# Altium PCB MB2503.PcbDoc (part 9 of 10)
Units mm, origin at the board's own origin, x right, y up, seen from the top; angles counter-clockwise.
Board outline 127 x 97 mm, 6 copper layers (Top Layer, Signal Layer 1, Signal Layer 2, Signal Layer 3, Signal Layer 4, Bottom Layer), stack 1.557 mm thick; 572 components, 468 nets, 2377 pads, 1704 vias.
Unrouted connection lines stored in the file: 3.
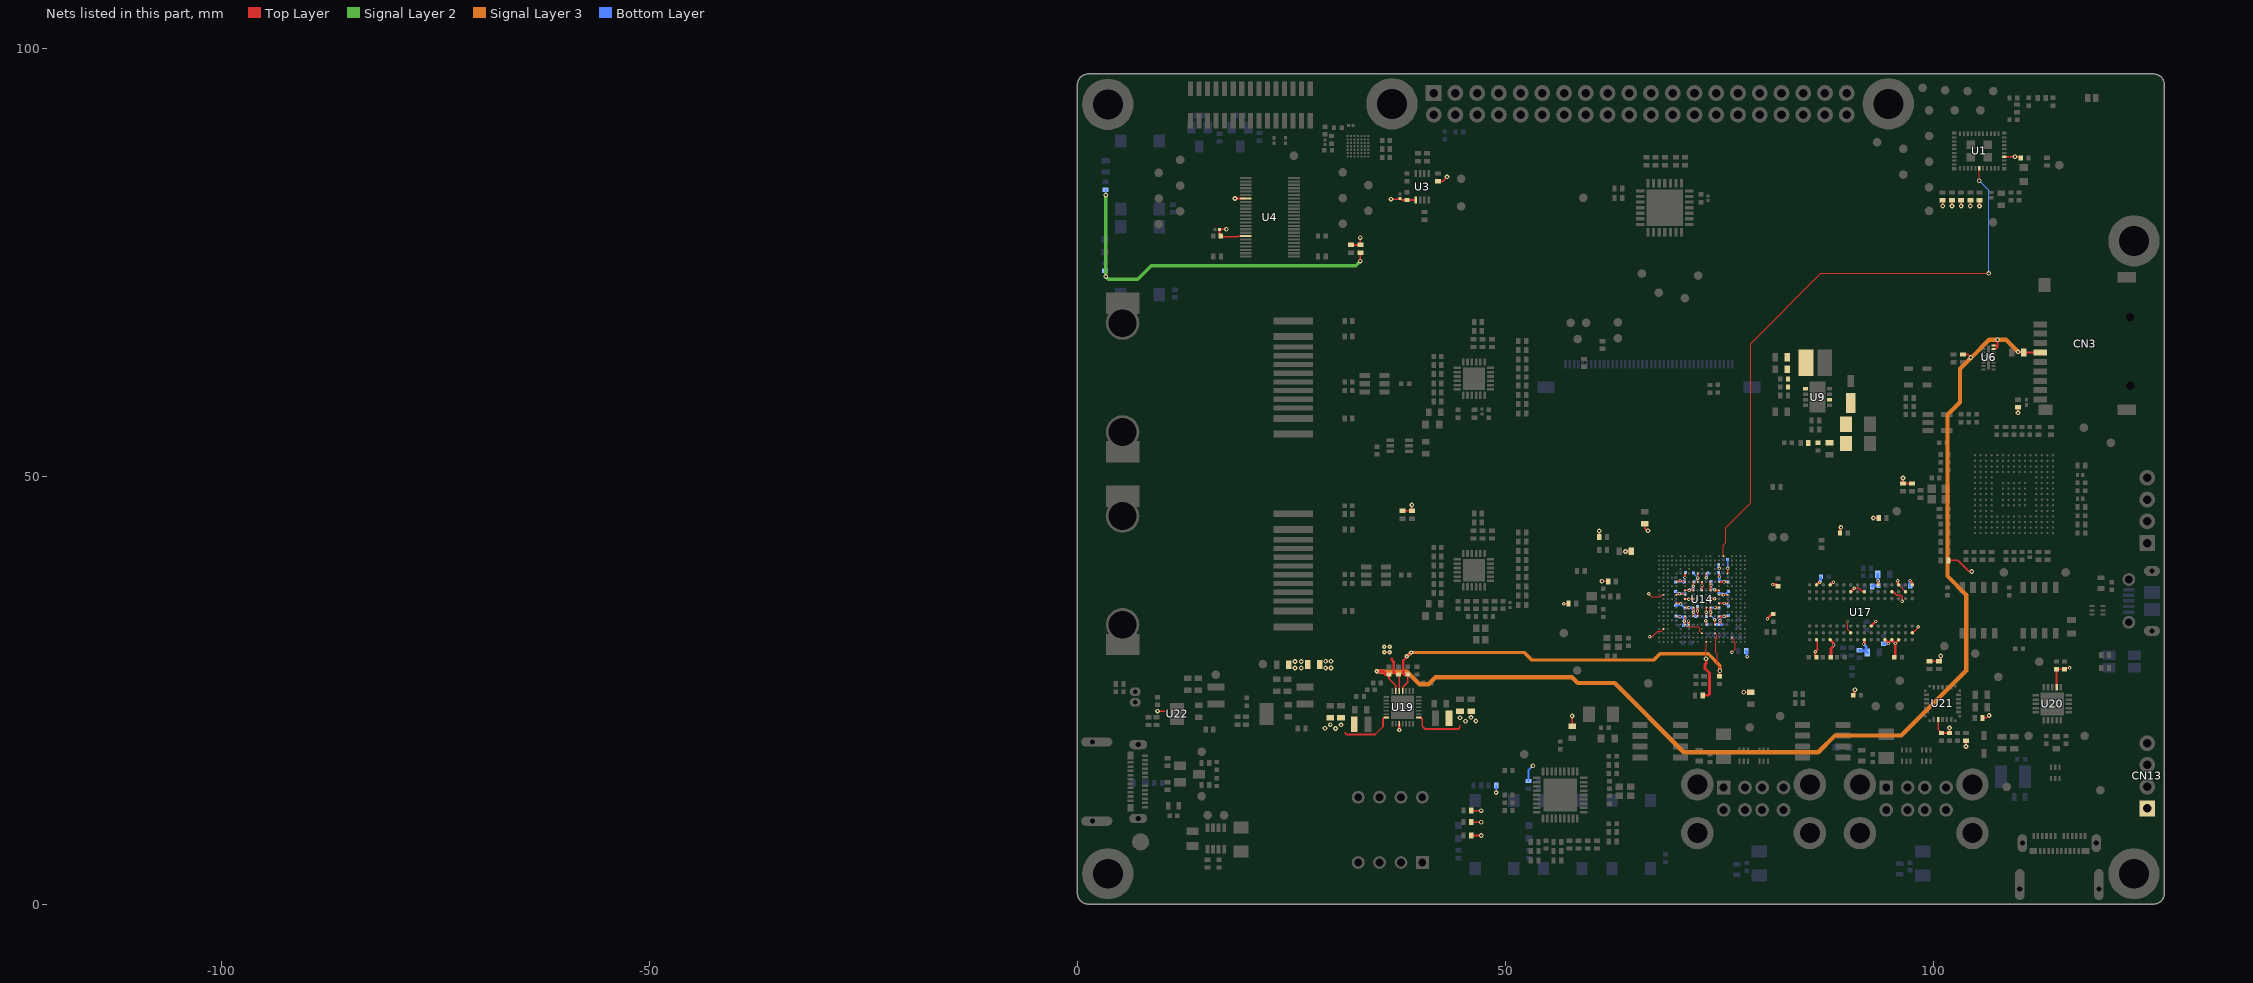
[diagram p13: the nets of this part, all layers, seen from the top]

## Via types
v1: diameter 0.55, hole 0.25, Top Layer to Bottom Layer, 1335 vias
v2: diameter 0.4, hole 0.2, Top Layer to Bottom Layer, 262 vias
v3: diameter 0.5, hole 0.2, Top Layer to Bottom Layer, 51 vias
v4: diameter 0.26, hole 0.1, Top Layer to Signal Layer 1, tented both sides, 29 vias
v5: diameter 0.5, hole 0.25, Top Layer to Bottom Layer, 18 vias
v6: diameter 0.4, hole 0.2, Top Layer to Bottom Layer, tented both sides, 9 vias

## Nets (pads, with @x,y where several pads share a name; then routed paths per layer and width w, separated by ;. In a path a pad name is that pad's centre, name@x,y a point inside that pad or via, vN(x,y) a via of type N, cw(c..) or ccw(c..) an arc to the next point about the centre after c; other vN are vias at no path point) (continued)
VDD: C15.2 C108.2 C109.2 C111.2 C138.2 C139.2 C171.2 C173.2 C176.2 C185.1 C190.2 C197.2 C201.2 C202.2 C205.2 C207.1 C208.2 C209.2 C214.1 C215.1 CN13.1 R14.1 R15.1 R16.1 R17.1 R18.1 R21.2 R46.1 R62.2 R63.2 R71.2 R72.2 R75.2 R82.2 R94.2 R108.2 R120.2 R121.1 R133.2 R141.2 R153.2 R154.2 R155.2 R172.2 R174.2 R180.2 R181.2 R187.2 R192.2 U1.36 U14.AA12 U14.C15 U14.E12 U14.E17 U14.G9 U14.G13 U14.J7 U14.J9 U14.J13 U14.K2 U14.M5 U14.N7 U14.N9 U14.N12 U14.R5 U14.R7 U14.R9 U14.R12 U14.U7 U14.U8 U14.V2 U14.W11 U14.Y18 U19.3 U19.19 U20.2 U21.3 U22.2 | length 117.3
  Top Layer w0.075: v2@66.75,36.2 67.046,35.904 68.079,35.904 68.302,36.127 68.452,36.127 U14.K2@68.475,36.15 ; v2(66.85,31.225) 67.15,31.225 67.825,31.9 68.225,31.9 U14.V2@68.475,32.15 ; U14.U7@70.975,32.65 71.224,32.401 72.512,32.401 72.727,32.187 72.727,32.186 72.728,32.184 72.728,31.897 U14.W11@72.975,31.65 ; v2(76.475,29.425) 76.85,29.8 76.85,30.425 76.725,30.55 76.725,30.899 U14.Y18@76.474,31.15
  Top Layer w0.09: v2@66.75,36.2 v2(66.75,36.25) ; U14.R5@69.975,33.65 70.002,33.623 70.405,33.623 70.449,33.58 70.444,33.575 v2(70.4,33.575) ; v1(73.45,28.675) 73.425,28.7 73.425,29.7 73.475,29.75 U14.AA12@73.475,30.65 ; U14.C15@74.975,39.65 74.988,39.638 74.988,39.188 75,39.2 v2(75,39.225)
  Top Layer w0.175: U14.J7@70.975,36.65 v2(71.475,36.65) U14.J9@71.975,36.65 71.975,37.125 v2(71.95,37.15) ; U14.R12@73.475,33.65 73.45,33.675 v2(73.45,34.1) 73.45,34.625 U14.N12@73.475,34.65
  Top Layer w0.2: v1(9.35,22.55) U22.2@10.175,22.55 ; v1(33.05,75.125) R21.2@33.05,76.125 ; v3(35.851,29.426) v3(36.5,29.425) ; C111.2@37.5,26.825 37.6,26.725 U19.19@37.6,24.9 ; C111.2@37.55,26.875 C111.2@37.6,26.825 ; C111.2@37.6,26.85 C111.2@37.625,26.875 ; R75.2@38,45.95 R71.2@39.1,45.95 39.075,45.975 v1(39.075,46.625) ; R153.2@46,8.025 v1(47.175,8.025) ; R154.2@46,9.575 v1(47.175,9.575) ; R155.2@46,10.925 v1(47.175,10.925) ; v2(56.825,35.1) 57.325,35.1 R108.2@57.375,35.15 ; R82.2@60.975,42.875 v1(60.975,43.6) ; v1(61.275,37.725) R192.2@62,37.725 ; U14.M5@69.975,35.15 69.979,35.146 70.375,35.146 70.446,35.075 v2(70.5,35.075) ; v2(70.9,33.05) 70.9,33.042 70.884,33.027 70.875,33.036 70.914,33.075 70.95,33.039 70.925,33.014 70.975,32.964 U14.U7@70.975,32.65 ; v2@70.925,33.136 70.975,33.186 U14.R7@70.975,33.65 ; U14.N7@70.975,34.65 71.425,34.65 v2(71.45,34.625) ; v2(71.4,33.075) 71.4,32.725 U14.U8@71.475,32.65 ; v2(71.95,37.15) 71.969,37.169 71.969,37.623 71.969,37.644 U14.G9@71.975,37.65 ; U14.R9@71.975,33.65 71.975,34.075 v2(71.95,34.1) 71.975,34.125 U14.N9@71.975,34.65 ; v2@73.475,38.148 U14.E12@73.475,38.65 ; U14.J13@73.975,36.65 73.975,37.178 74,37.203 v2@74,37.25 ; U14.G13@73.975,37.65 73.975,37.225 v2@74,37.25 ; v2(74.022,37.269) 74.02,37.269 v2@74,37.25 ; U14.E17@75.975,38.65 v2(75.975,39.225) ; v1(93,45.125) R72.2@93.625,45.125 ; v1(96.45,49.8) R62.2@96.45,49.15 R63.2@97.525,49.15 ; R120.2@99.575,28.375 R121.1@100.65,28.375 100.775,28.25 100.875,28.35 v1(100.875,29) ; U21.3@100.575,21.575 100.575,20.4 C138.2@100.975,20 C139.2@101.9,20 v1(101.9,20.6) ; v1(101.1,81.575) R14.1@101.1,82.25 ; R94.2@101.775,40.175 102.875,40.175 104.139,38.911 104.448,38.911 v1(104.5,38.858) ; v1(102.175,81.575) R15.1@102.175,82.25 ; v1(103.25,81.575) R16.1@103.25,82.25 ; v1(103.825,18.425) R141.2@103.825,19.1 ; v1(104.325,81.575) R17.1@104.325,82.25 ; v1(105.4,81.575) R18.1@105.4,82.25 ; R187.2@105.75,21.775 106.25,21.775 v1(106.525,22.05) ; U1.36@108.3,87.325 110.075,87.325 C15.2@110.225,87.175 ; v1(109.9,57.4) R46.1@109.9,58.05 ; U20.2@114.4,25.325 C108.2@114.4,27.45 C109.2@115.325,27.45 115.437,27.562 115.912,27.562 v2(115.95,27.6)
  Top Layer w0.25: v3(37.6,20.35) U19.3@37.6,21.1
  Top Layer w0.3: 36.725,28.65 36.725,28.53 36.95,28.305 36.95,27.106 37.126,26.93 37.57,26.93 C111.2@37.62,26.88 ; R133.2@73.05,24.4 73.674,24.4 73.85,24.576 73.85,27 73.325,27.525 73.325,28.023 73.45,28.148 v1(73.45,28.675)
  Signal Layer 2 w0.4: v1(3.3,73.325) v1@3.3,73.343 ; v1(3.3,82.85) v1@3.3,73.343 ; v1(33.05,75.125) 32.525,74.6 8.625,74.6 7.05,73.025 3.618,73.025 v1@3.3,73.343
  Bottom Layer w0.09: C185.1@73.999,37.649 C185.1@74,37.65
  Bottom Layer w0.15: v2(70.5,35.075) 70.5,35.05 70.85,34.7 70.9,34.7 C201.2@71,34.6
  Bottom Layer w0.2: R174.2@3.205,73.988 3.3,73.893 v1(3.3,73.325) ; v1(3.3,82.85) 3.3,83.483 R172.2@3.305,83.488 ; v1(48.925,13.041) R181.2@48.925,13.85 ; R180.2@52.692,14.387 52.692,15.658 v1(53.209,16.175) ; v2@72.003,33.965 72.275,33.693 C209.2@72.275,33.6 ; C176.2@73.52,38.545 C176.2@73.65,38.675 ; v2(75.975,39.225) C171.2@75.975,40.275
  Bottom Layer w0.3: C207.1@69.975,33.675 70.075,33.575 v2(70.4,33.575) 70.916,33.575 70.92,33.58 C205.2@71,33.5 70.875,33.375 70.903,33.347 70.9,33.343 v2(70.9,33.05) 70.9,33.028 70.898,33.027 70.875,33.05 70.888,33.063 70.888,32.751 70.825,32.688 70.825,32.575 C215.1@70.8,32.55 ; C197.2@69.975,34.875 70,34.9 70.123,34.9 70.248,35.025 70.252,35.025 70.255,35.028 70.383,35.028 70.41,35.056 70.481,35.056 v2(70.5,35.075) ; C201.2@71,34.6 71.025,34.625 v2(71.45,34.625) 71.825,34.625 C202.2@71.9,34.55 71.95,34.5 v2(71.95,34.1) ; C214.1@71.375,32.525 C214.1@71.35,32.55 71.375,32.575 71.375,33.05 v2(71.4,33.075) ; v2(71.475,36.65) 71.531,36.706 71.559,36.706 71.603,36.75 C190.2@71.925,36.75 71.95,36.775 v2(71.95,37.15) ; v2(73.45,34.1) 73.45,33.775 73.475,33.75 C208.2@73.525,33.7 ; v2@73.52,38.193 C176.2@73.52,38.545 ; C185.1@73.999,37.649 74.022,37.625 v2(74.022,37.269) ; C173.2@74.875,39.7 74.875,39.35 v2(75,39.225)
  other v1: 109.55,87.325
  other v2: 73.474,38.147
  other v3: 35.85,30.075 36.5,30.075
VDD_CORE: C110.2 C124.2 C126.2 C133.2 C188.2 C189.2 C195.1 C196.2 C199.2 C200.2 C203.1 C213.2 L9.2 U14.G11 U14.J11 U14.J15 U14.L7 U14.L9 U14.L13 U14.N10 U14.N13 U14.N15 U14.R10 U14.R13 U14.U12 U14.U14 U19.8 | length 20.2
  Top Layer w0.2: U19.8@39.9,21.8 40.125,21.8 40.275,21.65 40.275,20.775 40.575,20.475 44.558,20.475 44.675,20.592 44.675,20.809 ; C133.2@57.8,20.8 v1(57.8,21.975) ; U14.L7@70.975,35.65 71.425,35.65 v2(71.45,35.625) 71.475,35.65 U14.L9@71.975,35.65 ; v2(72.45,34.225) 72.45,34.625 U14.N10@72.475,34.65 ; U14.R10@72.475,33.65 v2@72.475,34.225 ; U14.J11@72.975,36.65 v2@72.975,37.198 ; v2(72.975,37.225) v2@72.975,37.198 ; U14.G11@72.975,37.65 v2@72.975,37.198 ; U14.U12@73.475,32.65 73.475,32.875 v2@73.475,33.1 ; U14.R13@73.975,33.65 v2(73.975,34.1) ; U14.N13@73.975,34.65 v2@73.975,34.125 ; U14.L13@73.975,35.65 74.448,35.65 74.473,35.675 74.471,35.677 v2(74.454,35.677) ; v2(74.45,36.725) 74.525,36.65 U14.J15@74.974,36.65 ; U14.U14@74.475,32.65 v2@74.475,33.175 ; v2(74.5,34.65) U14.N15@74.975,34.65 ; v1(77.85,24.75) C124.2@78.65,24.75 ; v2(73.975,34.1) v2@73.975,34.125 ; v2(73.975,34.1) v2@73.975,34.125
  Bottom Layer w0.2: v2(71.45,35.625) 71.675,35.625 71.7,35.65 C196.2@71.925,35.65 ; v2(72.45,34.225) 72.45,34.55 72.475,34.575 C203.1@72.45,34.6 ; C189.2@72.9,36.75 72.975,36.825 72.975,37.149 v2(72.975,37.225) ; v2@73.5,33.086 73.494,33.081 73.494,32.706 C213.2@73.55,32.65 ; C195.1@74,35.7 74.025,35.675 74.396,35.675 74.422,35.649 74.449,35.677 v2(74.454,35.677) 74.454,35.673 74.475,35.651 v2@74.461,35.637 ; C188.2@74,36.8 74.375,36.8 v2(74.45,36.725) ; v2@74.473,34.65 74.448,34.625 74.025,34.625 C200.2@74,34.6 73.975,34.575 v2(73.975,34.1) 73.994,34.081 73.994,33.938 74.025,33.907 74.025,33.712 74.425,33.312 74.425,33.302 74.475,33.252 v2(74.475,33.225) v2@74.475,33.2 ; v2@74.475,34.65 v2(74.5,34.65) 74.513,34.638 74.963,34.638 C199.2@74.975,34.625
  other v1: 45.35,21.375 46.55,21.4 44.7,21.775 45.975,21.825
  other v2: 73.4,33.1
VDD_CPU: C66.2 C72.2 C116.2 C129.2 C174.2 C177.1 C183.2 C186.2 C187.2 C191.1 C194.2 L11.2 R115.1 U14.E7 U14.E10 U14.G5 U14.G7 U14.G10 U14.K5 U14.K7 U19.28 | length 16.4
  Top Layer w0.2: 31.3,20.044 31.3,19.942 31.417,19.825 34.775,19.825 35.7,20.75 35.7,21.65 35.85,21.8 U19.28@36.1,21.8 ; v1@64.15,41.25 C72.2@64.7,41.25 ; C66.2@66.3,44.45 66.3,43.925 66.625,43.6 v1@66.652,43.627 ; U14.K5@69.975,36.15 69.982,36.15 70.107,36.275 v2(70.35,36.275) 70.363,36.263 70.855,36.263 70.968,36.15 U14.K7@70.975,36.15 ; U14.G5@69.975,37.65 69.983,37.65 70.094,37.761 70.386,37.761 v2(70.4,37.775) ; v2@70.4,37.721 70.416,37.737 70.58,37.737 70.596,37.721 70.896,37.721 70.967,37.65 U14.G7@70.975,37.65 ; U14.E7@70.975,38.65 70.976,38.649 70.976,38.169 v2(70.977,38.168) ; U14.G10@72.475,37.675 v2(72.475,38.1) ; v2@72.475,38.125 U14.E10@72.475,38.65
  Bottom Layer w0.09: C186.2@72,37.625 v2(72.475,38.1)
  Bottom Layer w0.1: v2(70.35,36.275) 70.473,36.275 70.474,36.276 v2@70.441,36.276 ; C177.1@72,38.675 72.125,38.55 72.125,38.479 72.248,38.356 72.319,38.356 72.418,38.257 v2@72.418,38.157
  Bottom Layer w0.15: C191.1@69.975,36.525 69.975,36.425 70.075,36.425 70.177,36.323 70.394,36.323 v2@70.441,36.276
  Bottom Layer w0.2: C187.2@70.9,37.625 70.939,37.664 70.939,38.13 v2(70.977,38.168) 71.001,38.192 71.001,38.626 C174.2@71.025,38.65
  Bottom Layer w0.3: C183.2@69.9,37.625 69.925,37.65 70.038,37.65 70.113,37.725 v2@70.4,37.725 ; v2(70.4,37.775) 70.427,37.775 70.477,37.725 70.521,37.725 70.523,37.723 70.699,37.723 70.772,37.65 70.875,37.65 C187.2@70.9,37.625 ; v2@70.473,36.275 70.502,36.275 70.536,36.241 70.966,36.241 C194.2@70.975,36.25
  other v1: 30.15,20.525 28.925,20.55 30.8,20.95 29.55,20.975 29,27.6 29.625,27.6 29,28.375 29.625,28.375 64.025,41.2 66.653,43.627
VDD_DDR: C70.2 C82.2 C94.2 C104.2 C105.2 C106.2 C112.2 C121.2 C172.2 C175.2 C178.2 C179.2 C181.2 C182.2 C184.2 C192.2 C193.2 C198.2 C204.1 C206.2 C211.2 C212.2 C218.2 R115.2 R116.2 R198.2 R207.1 R214.1 U14.E15 U14.G15 U14.G17 U14.K15 U14.K17 U14.M15 U14.M17 U14.R15 U14.R17 U14.U15 U17.A1 U17.A8 U17.B2 U17.C1 U17.C9 U17.D2 U17.D9 U17.E9 U17.F1 U17.G7 U17.H2 U17.H9 U17.K2 U17.K8 U17.N1 U17.N9 U17.R1 U17.R9 | length 42.2
  Top Layer w0.09: v2(89.975,33.025) 89.975,32.075 U17.K8@90.35,31.7
  Top Layer w0.1: U17.H2@91.905,36.535 U17.H2@91.945,36.495 ; U17.C1@95.945,37.295 U17.B2@96.745,36.495
  Top Layer w0.125: U17.R9@86.35,30.9 U17.R9@86.463,30.787
  Top Layer w0.15: U17.D2@95.145,36.495 95.325,36.495 95.715,36.104 96.135,36.104 96.35,35.89 v2(96.35,35.375)
  Top Layer w0.175: 86.463,29.763 U17.R9@86.463,30.787
  Top Layer w0.18: v2(90.75,36.9) 91.325,36.9
  Top Layer w0.2: U14.U15@74.974,32.65 75.075,32.75 v2(75.075,33.1) 75.075,33.55 74.975,33.65 75.525,33.65 v2(75.55,33.625) 75.575,33.65 U14.R17@75.974,33.65 ; U14.M15@74.975,35.15 U14.M17@75.975,35.15 ; U14.K15@74.975,36.15 74.982,36.157 75.468,36.157 v2(75.475,36.15) ; U14.G15@74.975,37.65 v2(75.55,37.65) 75.556,37.656 75.948,37.656 75.969,37.656 U14.G17@75.975,37.65 ; v2(74.975,38.225) U14.E15@74.975,38.65 ; v2@75.404,36.15 v2(75.475,36.15) ; U14.K17@75.974,36.15 v2(75.475,36.15) ; 91.325,36.9 91.69,36.535 U17.H2@91.905,36.535 ; U17.A8@97.55,31.7 97.6,31.7 98.212,32.312 98.212,32.386 v2(98.25,32.425)
  Top Layer w0.3: v2(80.625,33.35) 81.175,33.9 C94.2@81.3,33.9 ; v2(81.25,37.35) 81.65,37.35 C82.2@81.85,37.15 ; C105.2@86.35,28.85 86.2,29 v2(86.2,29.5) 86.463,29.763 ; U17.R1@86.35,37.3 86.631,37.581 86.731,37.581 v2@86.75,37.6 ; U17.N9@87.95,30.9 88.331,30.519 88.331,30.294 v2(88.35,30.275) 88.35,30.248 88.3,30.198 88.3,30.115 88.049,29.864 88.049,28.899 C106.2@88,28.85 ; U17.N1@87.95,37.3 88.231,37.581 88.331,37.581 v2@88.35,37.6 ; C70.2@89.1,43.37 89.152,43.422 89.152,43.977 v1(89.2,44.025) ; U17.K2@90.345,36.495 v2@90.719,36.869 ; C121.2@90.65,24.395 90.755,24.5 90.755,24.887 90.85,24.982 v1(90.85,25.05) ; v6(91.85,30.395) 91.85,30.422 91.958,30.53 91.958,30.887 U17.H9@91.96,30.89 ; U17.G7@92.745,32.495 v2(93.275,33.025) ; v2(93.545,37.795) 93.545,37.305 U17.F1@93.55,37.3 ; U17.E9@94.345,30.895 v6@94.745,30.495 ; v6@94.745,30.495 U17.D9@95.15,30.9 95.169,30.881 95.169,30.831 v6(95.55,30.45) ; C104.2@95.45,28.85 95.55,28.95 v6(95.55,30.45) ; v2(95.825,37.8) 95.825,37.452 95.945,37.332 U17.C1@95.945,37.295 ; U17.C9@95.95,30.9 95.931,30.881 95.931,30.831 v6(95.55,30.45) ; v6(97.275,37.8) 97.531,37.544 97.531,37.319 U17.A1@97.55,37.3
  Bottom Layer w0.15: C193.2@74.975,36.275 C193.2@75,36.25 ; v2@75.394,36.169 75.456,36.169 v2(75.475,36.15) 75.523,36.198 75.648,36.198 75.85,36.4 75.925,36.4 C192.2@76.025,36.5
  Bottom Layer w0.175: 74.925,32.65 74.975,32.7 ; C204.1@74.975,33.525 C204.1@74.975,33.625
  Bottom Layer w0.2: v2@75.575,35.1 75.588,35.087 75.734,35.087 75.895,34.925 75.975,34.925 C198.2@76.025,34.875
  Bottom Layer w0.3: C212.2@74.65,32.65 74.925,32.65 C211.2@75.2,32.65 ; C175.2@74.875,38.675 74.975,38.575 v2(74.975,38.225) 74.975,37.8 C184.2@75.1,37.675 75.125,37.65 v2(75.55,37.65) 75.57,37.655 cw(c75.628,37.36) 75.629,37.66 75.921,37.66 cw(c75.922,37.36) 75.984,37.654 C182.2@75.999,37.651 ; 74.975,32.7 75.075,32.8 v2(75.075,33.1) 75.075,33.425 C204.1@74.975,33.525 ; C204.1@75,33.625 v2(75.55,33.625) 75.569,33.644 75.84,33.644 75.921,33.725 76.025,33.725 C206.2@76.05,33.75 ; C193.2@75,36.25 75.314,36.25 v2@75.394,36.169 ; R198.2@78.125,29.575 78.219,29.481 78.219,28.984 78.25,28.952 v6(78.25,28.925) ; v2@86.75,37.6 86.75,37.627 86.817,37.693 86.817,38.12 86.841,38.145 C181.2@86.87,38.145 ; R207.1@91.375,29.675 91.462,29.588 92.105,29.588 C112.2@92.159,29.534 ; v6(91.85,30.395) 92.159,30.086 C112.2@92.159,29.534 ; R214.1@92.875,37.145 92.91,37.18 93.495,37.18 93.564,37.249 C179.2@93.564,37.251 ; C172.2@93.5,38.55 93.526,38.524 93.526,37.814 v2(93.545,37.795) ; v2@93.575,37.825 v2(93.545,37.795) ; C179.2@93.6,37.215 C179.2@93.564,37.251 ; C218.2@94.165,30.425 94.178,30.438 94.738,30.438 v6(94.75,30.45) ; v6(97.275,37.8) 97.275,37.225 C178.2@97.325,37.175 ; C112.2@92.159,29.534 92.275,29.418 C112.2@92.275,29.4 92.159,29.516 C112.2@92.159,29.534 ; v2(93.545,37.795) 93.564,37.776 C179.2@93.564,37.251
  other v1: 25.425,27.6 26.15,27.6 25.425,28.35 26.15,28.35
  other v2: 75.575,35.125 86.74,37.6 88.34,37.6
VDD_LS: C16.2 C17.2 C24.2 C25.2 R6.2 R20.1 R21.1 U3.1 U4.7 U4.18 | length 12.7
  Top Layer w0.2: v1(17.4,78.85) C24.2@16.6,78.85 16.6,78.2 16.825,77.975 18.672,77.975 18.747,78.05 U4.18@19.725,78.05 ; v1(18.4,82.45) U4.7@19.65,82.45 ; U4.18@19.1,78.05 U4.18@19.65,78.05 ; R20.1@31.975,77.025 R21.1@33.05,77.025 v1(33.05,77.875) ; v1(36.625,82.375) 37.65,82.375 C17.2@37.715,82.44 37.89,82.265 C16.2@38.515,82.265 U3.1@39.54,82.265 ; R6.2@42.14,84.465 42.148,84.473 42.673,84.473 v1(43.175,84.975)
VDD_SD: C27.2 C144.2 CN3.4 R34.2 U6.15 U6.16 U19.20 | length 132.5
  Top Layer w0.2: C144.2@36.375,26.85 C144.2@36.4,26.825 36.4,26.35 37.2,25.55 U19.20@37.2,24.9 ; R34.2@103.45,64.225 104.1,64.225 v1@104.45,63.875 ; U6.15@107.025,64.875 107.294,64.875 107.5,65.081 107.5,65.3 ; U6.16@107.025,65.275 107.475,65.275 107.5,65.3 ; v1(107.5,65.95) 107.5,65.3 ; v1@110,64.45 C27.2@110.575,64.45 CN3.4@112.5,64.45
  Top Layer w0.3: C144.2@36.412,26.825 C144.2@36.448,26.789
  Top Layer w0.4: v3(34.975,27.2) 35.673,27.2 35.993,26.88 36.345,26.88 C144.2@36.4,26.825
  Signal Layer 3 w0.5: v3@35,27.2 35.4,27.2 35.45,27.15 38.525,27.15 39.975,25.7 41.025,25.7 41.825,26.5 57.775,26.5 58.45,25.825 62.775,25.825 70.849,17.751 86.551,17.751 88.514,19.714 96.264,19.714 103.85,27.3 103.85,36.137 101.65,38.337 101.65,57.175 103.125,58.65 103.125,62.545 104.365,63.786 104.365,63.865 v1(104.375,63.875) 104.45,63.875 106.525,65.95 v1(107.5,65.95) 108.5,65.95 109.9,64.55 v1(109.9,64.525)
VDD_USB: C100.2 C119.2 U14.W14 U19.18 | length 49.5
  Top Layer w0.075: U14.W14@74.475,31.65 74.721,31.404 74.721,31.048 74.559,30.886 74.559,29.406 74.775,29.19 74.775,27.975 74.95,27.8
  Top Layer w0.2: U19.18@38,24.9 38,25.325 38.6,25.925 C100.2@38.6,26.825 ; 74.975,27.725 74.975,27.475 74.95,27.45 75.05,27.35 v1(75.05,27.275) 75.05,26.925 74.95,26.825 C119.2@75.15,26.625
  Top Layer w0.3: 38.055,28.476 38.055,26.945 38.173,26.827 C100.2@38.495,26.827 ; 38.075,28.475 38.075,28.496 38.475,28.896 v3(38.475,28.95) 38.512,28.95 38.962,29.4 v3(39,29.4)
  Signal Layer 3 w0.4: v3(38.475,28.95) 38.494,28.969 38.542,28.969 38.973,29.4 v3@38.975,29.4 ; v3(39,29.4) v3@38.975,29.4 ; v1@75.05,27.35 75.05,27.88 73.686,29.244 68.069,29.244 67.35,28.525 53.103,28.525 52.225,29.403 38.978,29.403 v3@38.975,29.4
VH: C45.2 C51.2 C52.2 C56.2 D2.2 R60.1 U9.6
VL: C29.1 C31.2 C34.2 L3.1 R35.2 U9.1
WL_HOST_WAKE: U1.27 U14.A16 | length 70.1
  Top Layer w0.075: U14.A16@75.475,40.65 75.475,41.275 75.475,41.931 75.75,42.206 75.75,43.125
  Top Layer w0.1: 75.75,43.125 75.75,43.983 78.65,46.883 78.65,65.475 86.875,73.7 v1(106.475,73.7) ; v1(105.375,84.525) U1.27@105.375,85.975
  Bottom Layer w0.1: v1(105.375,84.525) 106.475,83.425 v1(106.475,73.7)
pads on no net: CN1.16 CN1.17 CN1.18 CN1.19 CN1.20 CN1.21 CN1.22 CN1.23 CN1.24 CN1.25 CN1.26 CN1.27 CN1.28 CN1.29 CN1.30 CN3.13 CN3.NPTH1 CN3.NPTH2 CN4.9 CN7.A2 CN7.A3 CN7.A8 CN7.A10 CN7.A11 CN7.B2 CN7.B3 CN7.B8 CN7.B10 CN7.B11 CN10.4 CN12.A2 CN12.A3 CN12.A6 CN12.A7 CN12.A8 CN12.A10 CN12.A11 CN12.B2 CN12.B3 CN12.B6 CN12.B7 CN12.B8 CN12.B10 CN12.B11 CN15.9 CN16.5 CN16.6 CN16.13 CN16.14 CN16.21 CN16.22 L1.2 SW1.5 U1.13 U1.15 U1.16 U2.A1 U2.A3 U2.A5 U2.B1 U2.B2 U2.B5 U2.B6 U2.B7 U2.C2 U5.7 U5.10 U6.1 U6.2 U7.4 U9.5 U12.A1 U12.A2 U12.A3 U12.A4 U12.A5 U12.A8 U12.A9 U12.A11 U12.A12 U12.A13 U12.B1 U12.B2 U12.B3 U12.B4 U12.B5 U12.B6 U12.B7 U12.B8 U12.B9 U12.B10 U12.B11 U12.B12 U12.B13 U12.B15 U12.C2 U12.C3 U12.C4 U12.C11 U12.C12 U12.C13 U12.C14 U12.C15 U12.D1 U12.D2 U12.D3 U12.D4 U12.D10 U12.D11 U12.D13 U12.D14 U12.E1 U12.E2 U12.E3 U12.E4 U12.E12 U12.E13 U12.E14 U12.E15 U12.F1 U12.F4 U12.F14 U12.F15 U12.G4 U12.G14 U12.G15 U12.H1 U12.H2 U12.H3 U12.H4 U12.H14 U12.H15 U12.J2 U12.J3 U12.J4 U12.K1 U12.K2 U12.K3 U12.K12 U12.K14 U12.K15 U12.L1 U12.L12 U12.L13 U12.L14 U12.L15 U12.M2 U12.M3 U12.M4 U12.M5 U12.M7 U12.M12 U12.M13 U12.M14 U12.M15 U12.N2 U12.N4 U12.N5 U12.N6 U12.N7 U12.N11 U12.N13 U12.N14 U12.N15 U12.P2 U12.P4 U12.P5 U12.P6 U12.P7 U12.P8 U12.P9 U12.P10 U12.P11 U12.P12 U12.P13 U12.P14 U12.P15 U12.R2 U12.R3 U12.R6 U12.R7 U12.R8 U12.R9 U12.R10 U12.R11 U12.R12 U14.M3 U17.J1 U17.J9 U17.L1 U17.L9 U18.4 U19.6 U21.1 U21.2 U21.6 U21.7 U21.10 U21.11 U21.12 U21.23 U21.24 U25.2 U26.4 U27.4 U28.4 U29.4 U32.4 U42.4

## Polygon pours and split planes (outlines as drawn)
5V_VIN on Signal Layer 4 "5V_VIN_L05" (solid, pour order 224): 125.886,99.467 128.961,96.392 128.961,3.817 121.911,-3.233 -0.864,-3.233 -2.539,-1.558 -2.539,99.467
VDD_CPU on Signal Layer 4 "VDD_CPU_L05_P088" (solid, remove dead copper, pour order 88): 70.075,35.85 70.275,36.05 70.475,36.05 70.475,36.075 70.625,36.225 70.625,37.525 70.975,37.875 72.575,37.875 72.75,38.05 72.75,38.5 73.05,38.8 74.4,38.8 74.4,39.1 74.725,39.425 74.725,43.075 70.675,47.125 31.275,47.125 25.45,41.3 25.45,32.95 26.775,31.625 26.775,19.925 27.075,19.625 31.3,19.625 31.825,20.15 31.825,36.425 31.675,36.575 30.05,36.575 29.725,36.9 29.725,38.9 30.05,39.225 36.55,39.225 40.825,43.5 43.2,43.5 44.7,42 44.7,36.125 44.975,35.85
VBUSc on Signal Layer 4 "VBUSc_L05" (solid, pour order 102): 9.35,16.75 5.225,16.75 4.55,16.075 4.55,10.55 2149.456,-2134.256 8.875,6.325 13.15,6.325 14.55,7.725 14.55,9.4 10.125,13.825 10.125,15.975
VDD_DDR on Signal Layer 4 "VDD_DDR_L05" (solid, pour order 22): 79.95,24.303 81.153,23.1 89.05,23.1 90.325,24.367 90.619,24.369 92.763,26.513 97.734,26.484 99.525,28.275 99.525,29.55 100.9,30.925 100.9,34.85 95.6,40.15 93.05,40.15 88.15,45.05 85.197,45.05 84.7,45.05 78.5,51.25 73.75,51.25 72.15,52.85 25.65,52.85 19.275,46.475 19.275,27.45 19.625,27.1 26.35,27.1 26.7,27.45 26.7,31.425 25.275,32.85 25.275,41.425 31.1,47.25 70.7,47.25 74.8,43.15 74.8,37.125 75.3,36.625 75.3,33.725 74.85,33.275 74.85,32.855 78.05,29.655 78.05,28.6 78.375,28.275 78.375,25.878
VDD on Signal Layer 4 "VDD_L05_P096" (solid, remove dead copper, pour order 96): 70.3,35.8 70.7,36.2 70.7,37.5 71.025,37.825 72.65,37.825 72.8,37.975 72.8,38.425 73.15,38.775 74.275,38.775 74.275,38.95 75.075,39.75 76.225,39.75 76.325,39.65 76.325,38.9 75.975,38.55 74.925,38.55 74.775,38.4 74.775,37.1 74.65,36.975 73.475,36.975 73.35,37.1 73.35,37.375 73.2,37.525 72.825,37.525 72.7,37.4 72.7,37.05 72.575,36.925 72.2,36.925 71.675,36.4 71.675,36 71.6,35.925 71.3,35.925 71.15,35.775 71.15,35.55 71.3,35.4 71.55,35.4 71.675,35.275 71.675,34.825 72.175,34.325 72.175,34.05 72.275,33.95 72.625,33.95 72.725,34.05 72.725,34.475 72.8,34.55 73.575,34.55 73.65,34.475 73.65,33.775 73.375,33.5 72.25,33.5 71.55,32.8 71.55,27.825 69.875,26.15 45.7,26.15 43.2,28.65 32.225,28.65 31.95,28.925 31.95,36.45 32.05,36.55 35.6,36.55 36.35,35.8
VDD_CORE on Signal Layer 4 "VDD_CORE_L05_P078" (solid, remove dead copper, pour order 78): 71.65,30.575 71.675,30.6 71.675,32.8 72.275,33.4 73.425,33.4 73.7,33.675 73.7,34.475 73.6,34.575 73.525,34.575 72.775,34.575 72.675,34.475 72.675,34.1 72.55,33.975 72.35,33.975 72.225,34.1 72.225,34.35 71.725,34.85 71.725,35.275 71.6,35.4 71.325,35.4 71.225,35.5 71.225,35.75 71.35,35.875 71.6,35.875 71.7,35.975 71.7,36.35 72.25,36.9 72.6,36.9 72.75,37.05 72.75,37.35 72.85,37.45 73.1,37.45 73.2,37.35 73.2,37.05 73.3,36.95 74.825,36.95 75.2,36.575 75.2,33.775 74.75,33.325 74.75,32.725 77.95,29.525 77.95,28.575 78.225,28.3 78.225,23.15 75.9,20.825 44.4,20.825 44.125,21.1 44.125,24.25 45.825,25.95 69.8,25.95 71.625,27.775 71.625,30.575
1V8_PERIPH on Signal Layer 4 "1V8_PERIPH_L05_P214" (solid, pour order 214): 34.25,25.475 34.325,25.55 34.325,28.45 34.225,28.55 32.2,28.55 31.925,28.275 31.925,20.125 31.375,19.575 27.05,19.575 26.675,19.95 26.675,26.7 26.375,27 18.325,27 17.95,26.625 17.95,25.325 18.5,24.775 24.375,24.775 25.05,24.1 25.05,19 25.55,18.5 32.425,18.5 32.9,18.975 32.9,26.175 33,26.275 33.55,26.275 33.65,26.175 33.65,25.55 33.725,25.475
3V3_SW on Signal Layer 4 "3V3_SW_L05" (solid, pour order 197): 59.1,17.4 60,16.5 61,16.5 61.487,16.487 62.525,15.45 62.525,7 60.25,4.725 51.725,4.725 49.775,6.675 49.775,14.2 52.975,17.4
1V8_PERIPH on Signal Layer 4 "1V8_PERIPH_L05" (solid, pour order 213): 40.2,88.725 40.2,77.45 38,75.25 4.75,75.25 3.825,74.325 3.825,25.45 3.225,24.85 -0.55,24.85 -0.55,75.25 -0.55,96.425 0.475,97.45 39.825,97.45 40.175,97.025 40.2,97
NetC221_2 on Signal Layer 4 "NetC221_2" (solid, pour order 178): 108.95,16.925 107.625,18.25 107.625,22.85 106.45,24.025 106.45,24.8 107.425,25.775 112.625,25.775 115.425,28.575 115.425,31.1 115.975,31.65 116.875,31.65 117.35,31.175 117.35,22.775 111.5,16.925
3V3_STLK on Signal Layer 4 "3V3_STLK_L05" (solid, pour order 188): 97.8,45.9 97.8,43.712 100.965,40.547 100.965,38.735 101.762,37.937 117.837,37.937 120.75,35.025 120.75,28.075 121.975,26.85 127.225,26.85 127.3,26.925 127.3,58.775 104.525,58.775 97.8,52.05
NetC71_2 on Signal Layer 4 "NetC71_2" (solid, pour order 20): 30.125,39.05 36.6,39.05 40.55,43 42.4,43 43.725,41.675 43.725,40.831 43.725,35.875 42.35,34.5 37.85,34.5 35.65,36.7 30.1,36.7 29.85,36.95 29.85,38.775
NetC28_2 on Signal Layer 4 "NetC28_2" (solid, pour order 124): 30.125,61.58 36.6,61.58 39.825,64.805 43.125,64.805 43.725,64.205 43.725,63.361 43.196,62.832 43.196,57.876 42.475,57.155 40.02,57.155 39.225,57.95 36.93,57.95 30.375,57.95 29.85,58.475 29.85,61.305
NetC221_2 on Signal Layer 4 "NetC221_2" (solid, pour order 128): 117.9,11.45 117.9,6.5 116.3,4.9 113.275,4.9 111.425,6.75 111.463,8.913 110.625,9.75 110.625,14.175 111.3,14.85 115.6,14.85 117.9,12.55
NetC87_2 on Signal Layer 4 "NetC87_2" (solid, pour order 139): 105.2,30.975 105.75,31.525 114.325,31.525 114.95,30.9 114.95,30.025 114.375,29.45 105.425,29.45 105.2,29.675
GND on Top Layer "GND_L01_P001" (solid, remove dead copper, pour order 223): 2.466,97.964 128.191,97.964 128.641,97.514 128.641,1.289 124.741,-2.611 1.366,-2.611 -2.734,1.489 -2.734,97.675
5V_VIN on Top Layer "5V_VIN_L01_P209" (solid, pour order 209): 24.15,22.225 25.25,22.225 25.375,22.1 25.375,21.1 25.25,20.975 24.125,20.975 24.025,21.075 24.025,21.6 23.925,21.7 23.275,21.7 23.225,21.75 23.225,22.05 23.275,22.1 24.025,22.1
5V_VIN on Top Layer "5V_VIN_L01_P210" (solid, pour order 210): 13.625,22.175 14.825,22.175 14.9,22.1 14.9,21.1 14.725,20.925 13.7,20.925 13.55,21.075 13.55,21.6 13.45,21.7 12.8,21.7 12.75,21.75 12.75,22.05 12.8,22.1 13.55,22.1
VDD_CPU on Top Layer "VDD_CPU_L01_P211" (solid, pour order 211): 27.95,28.75 27.85,28.65 27.85,27.375 27.95,27.275 29.925,27.275 30.075,27.425 30.075,28.575 29.9,28.75
NetC127_2 on Top Layer "NetC127_2_L01" (solid, pour order 216): 22.65,28.575 22.825,28.75 23.625,28.75 23.75,28.625 23.75,27.35 23.925,27.175 27.75,27.175 27.9,27.025 27.9,24.875 27.775,24.75 25.35,24.75 25.25,24.85 25.25,25.775 25.175,25.85 22.875,25.85 22.65,26.075
VDD_DDR on Top Layer "VDD_DDR_L01_P215" (solid, pour order 215): 24.325,27.275 24.25,27.35 24.25,28.625 24.375,28.75 27.25,28.75 27.35,28.65 27.35,27.375 27.25,27.275
NetL6_1 on Top Layer "NetL6_1_L01" (solid, pour order 201): 27.622,22.322 23.647,22.328 23.6,22.375 23.6,22.729 23.622,22.75 25.15,22.75 25.275,22.875 25.275,23.825 25.4,23.95 27.775,23.95 27.9,23.825 27.9,22.6
NetL8_1 on Top Layer "NetL8_1_L01" (solid, pour order 171): 17.197,22.272 13.222,22.278 13.175,22.325 13.175,22.75 13.25,22.821 14.696,22.821 14.85,22.975 14.85,23.825 14.975,23.95 17.325,23.95 17.475,23.8 17.475,22.55
NetL9_1 on Top Layer "NETL9_1_L01" (solid, pour order 122): 40.35,22.7 40.125,22.7 40.125,22.55 40.188,22.55 40.5,22.238 40.5,21.225 40.975,20.75 42.175,20.75 42.175,22.7
5V_VIN on Top Layer "5V_VIN_L01_P208" (solid, pour order 208): 16.225,8 16.6,7.625 21.025,7.625 21.475,8.075 21.475,9.375 19.725,11.125 18.2,11.125 17.95,10.875 17.95,10 17.725,9.775 16.525,9.775 16.225,9.475
VBUSc on Top Layer "VBUSC_L01_P202" (solid, pour order 202): 9.65,12 9.65,7.925 9.95,7.625 15.75,7.625 16.125,8 16.125,9.475 15.825,9.775 11.125,9.775 11.025,9.875 11.025,12 10.85,12.175 9.825,12.175
3V3_AO on Top Layer "3V3_AO_L01" (solid, pour order 200): 12.225,27.475 12.575,27.825 14.3,27.825 14.825,27.3 17.125,27.3 17.475,26.95 17.475,24.825 17.375,24.725 14.825,24.725 14.7,24.85 14.7,25.775 14.55,25.925 12.45,25.925 12.225,26.15
VDD_CORE on Top Layer "VDD_CORE_L01_P001" (solid, remove dead copper, pour order 72): 46.925,22.45 46.925,21.075 46.675,20.825 43.1,20.825 43.1,22.6 44,22.6 44.15,22.75 45.2,22.75 46.625,22.75
VDD_CPU on Top Layer "VDD_CPU_L01_P001" (solid, remove dead copper, pour order 112): 29.125,21.6 29.125,22.1 31.85,22.1 32.05,21.9 32.7,21.9 32.7,20.15 32.675,20.125 32,20.125 31.925,20.05 28.9,20.05 28.575,20.375 28.575,21.25 28.925,21.6
5V_VIN on Top Layer "5V_VIN_L01_P002" (solid, remove dead copper, pour order 90): 39.075,25.225 39.325,25.225 39.525,25.425 40.775,25.425 40.9,25.55 40.9,26.125 41.2,26.425 41.2,26.625 41.025,26.8 40.275,26.8 40.075,26.6 40.075,26.425 39.075,25.425
VDD_USB on Top Layer "VDD_USB_L01_P202" (solid, remove dead copper, pour order 199): 38.225,26.8 38.975,26.8 38.975,26.1 38.1,25.225 37.9,25.225 37.875,25.25 37.875,25.825 38.225,26.175 38.225,26.825
3V3_AO on Top Layer "3V3_AO_L01_P002" (solid, remove dead copper, pour order 170): 34.15,53.95 33.9,54.2 32.9,54.2 32.65,53.95 32.65,53.2 32.925,52.925 33.875,52.925 34.15,53.2
5V_VIN on Top Layer "5V_VIN_L01_P001" (solid, remove dead copper, pour order 98): 36.9,25.2 36.925,25.225 36.925,25.425 35.6,26.75 34.85,26.75 34.7,26.6 34.7,26.35 34.9,26.15 35.225,26.125 35.225,25.45 36.4,25.45 36.65,25.2
5V_VIN on Top Layer "5V_VIN_L01_P005" (solid, remove dead copper, pour order 80): 39.775,23.1 40.275,23.1 40.925,23.75 40.925,24.6 41.125,24.8 42,24.8 42.175,24.625 42.175,24.05 41.925,23.8 41.925,23.125 41.7,22.9 39.775,22.9
NetL11_1 on Top Layer "NetL11_1" (solid, remove dead copper, pour order 108): 35.775,22.7 35.45,22.7 34.775,22.025 33.875,22.025 33.65,21.8 33.65,20.2 33.75,20.1 34.65,20.1 35.4,20.85 35.4,22.125 35.775,22.5
VDD on Top Layer "VDD_L01_P001" (solid, remove dead copper, pour order 198): 37.5,25.225 37.475,25.25 37.475,25.85 37.125,26.2 37.125,27.075 37.825,27.075 37.825,25.95 37.725,25.85 37.725,25.25 37.7,25.225
VDD_SD on Top Layer "VDD_SD_L01_P001" (solid, remove dead copper, pour order 193): 37.075,25.25 37.075,25.425 36.025,26.475 36.025,26.816 36.725,26.816 36.725,26.425 37.325,25.825 37.325,25.25 37.3,25.225 37.1,25.225
VDD on Top Layer "VDD_L01_P002" (solid, remove dead copper, pour order 104): 35.475,28.55 35.775,28.25 37.1,28.25 37.1,29.55 36.925,29.725 36.925,30.275 36.7,30.5 35.7,30.5 35.475,30.275
GND on Top Layer "GND_L01_P003" (solid, pour order 218): 98.025,94.95 96.15,96.825 92.8,96.825 91.475,95.5 91.475,91.8 93.275,90 96.9,90 98.025,91.125
5V_VIN on Top Layer "5V_VIN_L01_P004" (solid, remove dead copper, pour order 110): 33.6,23.25 33.45,23.4 33.45,23.708 33.542,23.8 34.5,23.8 35.2,23.1 35.65,23.1 34.8,22.25 33.7,22.25 33.6,22.35
3V3_SW on Top Layer "3V3_SW_L01_P001" (solid, remove dead copper, pour order 168): 38.45,53.4 38.45,55.65 39.25,56.45 41,56.45 41,53.85 40.9,53.75 40,53.75 39.65,53.4
NetC87_2 on Top Layer "NetC87_2" (solid, pour order 182): 112.525,35.6 112.675,35.75 116.25,35.75 116.85,35.15 116.85,32.75 116.575,32.475 115.675,32.475 115.3,32.1 115.3,30.65 114.775,30.125 112.75,30.125 112.525,30.35
GND on Top Layer "GND_L01_P006" (solid, pour order 221): 40.025,94.95 38.15,96.825 34.8,96.825 33.475,95.5 33.475,91.8 35.275,90 38.9,90 40.025,91.125
VL on Top Layer "VL_L01" (solid, pour order 190): 82.35,64.675 82.35,62 82.6,61.75 82.6,60.025 82.7,59.925 85.4,59.925 85.45,59.975 85.45,61.325 85.5,61.375 85.9,61.375 86.2,61.675 86.2,64.925 86,65.125 82.8,65.125 82.375,64.7
VH on Top Layer "VH_L01" (solid, pour order 192): 88.675,59.275 89.225,59.825 91.45,59.825 91.55,59.725 91.55,57.5 91.05,57 91.05,53 90.625,52.575 89.15,52.575 88.525,53.2 87.475,53.2 87.2,53.475 85.1,53.475 85,53.575 85,54.275 85.1,54.375 87.925,54.375 88.7,55.15 88.7,58.325 88.425,58.6 87.575,58.6 87.5,58.675 87.5,59.2 87.575,59.275
NetC28_2 on Top Layer "NetC28_2" (solid, pour order 179): 24.7,61.53 22.655,61.53 22.475,61.35 22.475,59.75 22.695,59.53 31.6,59.53 31.675,59.605 31.675,61.38 31.525,61.53
NetC71_2 on Top Layer "NetC71_2" (solid, pour order 177): 22.65,39 22.325,38.675 22.325,37.3 22.625,37 31.6,37 31.675,37.075 31.675,38.85 31.525,39
NetD2_1 on Top Layer "NetD2_1" (solid, pour order 191): 86.375,65.05 86.375,61.475 86.525,61.325 87.375,61.325 87.5,61.2 87.5,60 87.575,59.925 90.575,59.925 90.975,60.325 90.975,62.75 88.525,65.2 86.525,65.2
GND on Top Layer "GND_L01_P005" (solid, pour order 220): 6.825,94.9 4.95,96.775 1.6,96.775 0.275,95.45 0.275,91.75 2.075,89.95 5.7,89.95 6.825,91.075
GND on Top Layer "GND_L01_P004" (solid, pour order 219): 126.775,78.95 124.9,80.825 121.55,80.825 120.225,79.5 120.225,75.8 121.85,74.175 125.825,74.175 126.775,75.125
GND on Top Layer "GND_L01_P007" (solid, pour order 222): 126.775,5 124.9,6.875 121.55,6.875 120.225,5.55 120.225,1.85 122.025,0.05 125.65,0.05 126.775,1.175
GND on Top Layer "GND_L01_P002" (solid, pour order 217): 6.875,5.05 5,6.925 1.65,6.925 0.325,5.6 0.325,1.9 2.125,0.1 5.75,0.1 6.875,1.225
3V3_STLK on Top Layer "3V3_STLK_L01_P001" (solid, pour order 189): 105.875,58.2 106.025,58.05 106.025,57 105.85,56.825 100.85,56.825 100.75,56.925 100.75,57.75 101.2,58.2
NetC36_1 on Top Layer "NetC36_1" (solid, pour order 187): 97.325,56.825 97.425,56.725 100.1,56.725 100.225,56.6 100.225,55.925 100.15,55.85 98.6,55.85 98.4,55.65 98.4,54.875 98.6,54.675 100.1,54.675 100.7,55.275 100.7,57.55 100.475,57.775 98.875,57.775 98.3,58.35 98.3,59.475 98.075,59.7 97.45,59.7 97.325,59.575
NetD1_2 on Top Layer "NetD1_2" (solid, pour order 186): 98.05,60.475 97.275,59.7 97.275,58.75 97.15,58.625 96.425,58.625 96.275,58.775 96.275,63.025 96.4,63.15 97.825,63.15 98.05,62.925
5V_VIN on Top Layer "5V_VIN_L01_P003" (solid, pour order 185): 105,35.725 105.15,35.575 105.15,30.75 104.675,30.275 102.875,30.275 101.975,31.175 101.975,35.1 102.6,35.725
SRC_GDCS on Top Layer "SRC_GDCS" (solid, pour order 184): 104,38.25 104.5,38.75 107.925,38.75 108.425,38.25 108.425,36.525 108.05,36.15 106.675,36.15 106.475,36.35 106.475,37.625 106.225,37.875 105.525,37.875 105.325,37.675 105.325,36.3 105.15,36.125 104.25,36.125 104,36.375
NetC87_2 on Top Layer "NetC87_2" (solid, pour order 183): 105.3,35.575 105.55,35.825 107.875,35.825 108.3,35.4 108.3,30.725 107.7,30.125 105.625,30.125 105.3,30.45
SNK_GDCS on Top Layer "SNK_GDCS" (solid, pour order 181): 111.125,38.25 111.625,38.75 115.05,38.75 115.55,38.25 115.55,36.525 115.175,36.15 113.8,36.15 113.6,36.35 113.6,37.625 113.35,37.875 112.65,37.875 112.45,37.675 112.45,36.3 112.275,36.125 111.375,36.125 111.125,36.375
PWR_ON_DB on Top Layer "PWR_ON_DB" (solid, pour order 180): 112.35,29.525 112.125,29.3 110.175,29.3 110.05,29.425 110.05,30.35 109.4,31 109.4,35.575 109.575,35.75 112.175,35.75 112.35,35.575
GND on Bottom Layer "GND_L06_P001" (solid, remove dead copper, pour order 162): -0.206,97.747 125.519,97.747 125.969,97.297 125.969,1.072 121.944,-2.953 0.544,-2.953 -5.531,3.122 -5.531,97.451
GND on Bottom Layer "GND_L06_P006" (solid, pour order 173): 91.475,94.95 93.35,96.825 96.7,96.825 98.025,95.5 98.025,91.8 96.225,90 92.6,90 91.475,91.125
GND on Bottom Layer "GND_L06_P002" (solid, pour order 163): 5.05,96.675 6.925,94.8 6.925,91.45 5.6,90.125 1.9,90.125 0.1,91.925 0.1,95.55 1.225,96.675
GND on Bottom Layer "GND_L06_P003" (solid, pour order 164): 4.95,6.825 6.825,4.95 6.825,1.6 5.5,0.275 1.8,0.275 0,2.075 0,5.7 1.125,6.825
GND on Bottom Layer "GND_L06_P004" (solid, pour order 165): 120.175,5 122.05,6.875 125.4,6.875 126.725,5.55 126.725,1.85 124.925,0.05 121.3,0.05 120.175,1.175
GND on Bottom Layer "GND_L06_P005" (solid, pour order 166): 120.125,79 122,80.875 125.35,80.875 126.675,79.55 126.675,75.85 124.875,74.05 121.25,74.05 120.125,75.175
GND on Bottom Layer "GND_L06_P007" (solid, pour order 174): 33.475,94.95 35.35,96.825 38.7,96.825 40.025,95.5 40.025,91.8 38.225,90 34.6,90 33.475,91.125
NetC221_2 on Bottom Layer "NetC221_2" (solid, pour order 161): 110.4,17.75 111.375,17.75 112.025,17.1 112.025,12.1 111.575,11.65 110.375,11.65 110.1,11.925 110.1,13.025 109.525,13.6 109.525,15.85 110.25,16.575 110.25,17.6
VDD on Signal Layer 3 "VDD_L04" (solid, pour order 225): 127.35,99.75 130.425,96.675 130.425,4.1 123.375,-2.95 1.825,-2.95 -2.3,1.175 -2.3,99.75
3V3_AO on Signal Layer 3 "3V3_AO_L04" (solid, pour order 120): 39.383,87.383 22.683,87.383 15.575,80.275 15.562,72.262 15.525,72.225 15.525,58.5 20.025,54 27.75,54 29.225,55.475 32.375,55.475 33.7,54.15 33.7,50.05 38.25,45.5 50.59,45.5 50.8,45.3 54.25,41.85 54.25,39.299 52.987,38.013 48.24,37.99 43.25,33 39.375,33 38.8,33.575 24.3,33.575 17.625,26.9 1.3,26.9 -1.55,29.75 -1.55,97.9 107.75,97.9 107.75,85.125 108.475,84.4 108.475,83.2 107.975,82.7 75.625,82.7 74.225,81.3 72.9,81.3 71.713,82.488 71.725,86.325 70.667,87.383 68.142,87.383
1V8_PERIPH on Signal Layer 3 "1V8_PERIPH_L04_P175" (solid, pour order 175): 18.575,26.825 18.85,26.55 18.85,25.225 18.575,24.95 0.675,24.95 0.5,25.125 0.5,26.65 0.675,26.825
VDD_LS on Signal Layer 3 "VDD_LS_L04" (solid, pour order 116): 21.75,78 22.75,79 25.75,79 27.25,77.5 33.325,77.5 37.5,81.675 37.5,83.312 38.338,84.15 43.05,84.15 43.458,84.557 43.458,86.917 43.1,87.275 39,87.275 22.8,87.275 18.725,83.2 17,81.475 17,78.73 17.73,78
3V3_SW on Signal Layer 3 "3V3_SW_L04" (solid, pour order 126): 40.475,57 39.5,56.025 39.5,54 40,53.5 44.5,53.5 45.25,54.25 49.225,54.25 53.5,58.525 53.5,66.275 52.225,67.55 40.825,67.55 40.475,67.2
GND on Signal Layer 1 "GND_L02_P156" (solid, remove dead copper, pour order 156): 1.325,98.675 127.05,98.675 127.5,98.225 127.5,2 122.975,-2.525 1.375,-2.525 -5.2,4.05 -5.2,98.312
GND on Signal Layer 2 "GND_L03_P152" (solid, remove dead copper, pour order 152): 0.5,97 126.475,97 126.475,0.9 126.1,0.525 0.5,0.525

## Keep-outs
Keep-Out Layer:
  region: 0,0 0,97 127,97 127,0 2,0 2,2.5 124.5,2.5 124.5,94.5 2.5,94.5 2.5,0

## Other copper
Top Layer:
  region: 126,83.575 ccw(c126.05,83.575) 126.05,83.525 126.45,83.525 ccw(c126.45,83.575) 126.5,83.575 126.5,94.475 ccw(c126.45,94.475) 126.45,94.525 118.875,94.525 118.875,94.025 126,94.025
  pour cut-out: 117,95.45 cw(c116.925,95.45) 116.925,95.375 109.8,95.375 ccw(c109.8,94.2) 108.625,94.2 108.625,91.2 cw(c108.55,91.2) 108.55,91.125 108.075,91.125 ccw(c108.075,90.975) 107.925,90.975 107.925,88.475 ccw(c108,88.475) 108,88.4 108.904,88.4 ccw(c108.904,90.472) 110.975,90.472 110.975,92.894 cw(c111.106,92.894) 111.106,93.025 116.925,93.025 cw(c116.925,92.95) 117,92.95 117,83 128.05,83 128.05,97.4 117,97.4
  pour cut-out: 27.35,28.65 27.85,28.65 27.85,27.35 27.35,27.35
  pour cut-out: 12.25,25.925 14.75,25.925 14.75,25.375 12.25,25.375
  pour cut-out: 23.75,28.625 24.25,28.625 24.25,27.325 23.75,27.325
  pour cut-out: 22.675,25.85 25.175,25.85 25.175,25.3 22.675,25.3
  pour cut-out: 20.65,23.7 23.55,23.7 23.55,20.725 20.65,20.725
  pour cut-out: 11.025,12.25 11.575,12.25 11.575,10.75 11.025,10.75
  pour cut-out: 14.45,7.625 17.9,7.625 17.9,6.875 14.45,6.875
  pour cut-out: 18.2,7.625 20,7.625 20,6.875 18.2,6.875
  pour cut-out: 12.75,7.625 14.15,7.625 14.15,7.275 12.75,7.275
  pour cut-out: 10.15,23.725 13.15,23.725 13.175,23.7 13.175,20.725 10.175,20.725
  pour cut-out: 41.05,26.225 41.05,25.475 40.9,25.475 40.9,26.225
  pour cut-out: 44.075,23.625 46.625,23.625 46.625,22.925 44.075,22.925
  pour cut-out: 42.225,22.775 43.025,22.775 43.025,20.625 42.225,20.625
  pour cut-out: 42.75,24.05 42.75,22.8 42.25,22.8 42.25,24.05
  pour cut-out: 32.75,23.35 32.75,19.95 32.775,19.925 33.45,19.925 33.45,23.35
  pour cut-out: 28.925,22.875 31.425,22.875 31.425,22.2 28.925,22.2
  pour cut-out: 32.825,23.875 33.125,23.875 33.15,23.9 33.15,24.625 32.825,24.625
  pour cut-out: 34.5,25.425 34.5,24.725 34.2,24.725 34.2,25.425
  pour cut-out: 34.8,26.15 35.15,26.15 35.15,25.45 34.8,25.45
  pour cut-out: 36.025,27.475 40.05,27.475 40.05,27.15 36.025,27.15
  pour cut-out: 36.425,24.575 39.575,24.575 39.575,21.425 36.4,21.425
  pour cut-out: 35.625,24.05 35.187,24.487 34.95,24.725 35.475,24.725 35.625,24.875 35.625,25.4 36.425,25.4 36.425,24.05
  pour cut-out: 36.244,20.375 35.575,20.375 35.575,20.45 36.244,20.45
  pour cut-out: 56.5,24.125 56.225,24.4 56.35,24.525 56.625,24.25
  pour cut-out: 52.675,23.275 52.775,23.175 53.55,23.175 53.85,23.475 53.85,23.8 53.65,24 52.675,24
  pour cut-out: 49.15,50.1 48.825,49.775 48.975,49.625 49.3,49.95
  pour cut-out: 39.3,20.375 40.4,20.375 40.4,20.45 39.3,20.45
  pour cut-out: 42.85,23 43.15,22.7 43.1,22.65 42.8,22.95
  pour cut-out: 32.65,22.325 32.65,22 32.775,22 32.775,22.325
  pour cut-out: 31.075,90.45 34.675,90.45 34.675,86.55 31.075,86.55
  pour cut-out: 104.75,50.025 103.15,51.625 101.775,51.625 101.775,50.7 103.325,50.7 104.55,49.475 105.075,49.475
  pour cut-out: 116.4,43.375 115.35,43.375 114.55,44.175 114.55,45.225 114.15,45.625 114.15,47.725 112.675,49.2 112.675,50.38 112.948,50.653 112.975,50.625 116.975,50.625 117.45,50.15 117.45,43.46 117.205,43.215
  pour cut-out: 108.5,41.15 108.5,42.05 109.05,42.6 109.05,43.5 111.575,43.5 111.725,43.35 111.725,42.475 112.275,41.925 112.275,41.15
  pour cut-out: 71.425,62.45 85.75,76.775 104.05,76.775 104.775,76.05 106.875,76.05 107.231,75.694 107.037,75.5 100.575,75.5 99.875,74.8 100.45,74.225 105.7,74.225 106.075,73.85 105.875,73.65 104,73.65 103.6,73.25 102.725,73.25 101.625,72.15 87.375,72.15 86.625,72.9 86.625,75.1 86.225,75.5 85.775,75.5 72.05,61.775 71.175,61.775
  pour cut-out: 72.725,55.9 76.25,55.9 76.3,55.95 76.3,50.2 75.4,49.3 73.9,49.3 72.725,50.475
  pour cut-out: 69.475,49.175 69.475,61.85 69.575,61.95 72.425,61.95 72.525,61.85 72.525,49.075 71.825,48.375 69.925,48.375
  pour cut-out: 65.525,61.45 66.725,61.45 66.775,61.4 66.775,55.975 66.4,55.6 66.325,55.675 65.625,55.675
  pour cut-out: 62.575,47.7 63.325,47.7 63.675,48.05 63.675,53.05 62.82,53.905 61.493,53.905 61.493,53.818 61.125,53.45 61.125,52.575 62.575,51.125
  pour cut-out: 61.2,50.891 61.2,43.7 60.575,43.075 60.575,40.85 61.375,40.05 61.425,40.1 62.475,40.1 62.962,40.587 62.962,44.088 61.95,45.1 61.95,50.825
  pour cut-out: 59.475,44.2 59.475,49.025 59.525,49.075 59.55,49.05 60.15,49.05 60.4,48.8 60.4,44.325 60.1,44.025
  pour cut-out: 52.5,54.35 54.7,54.35 54.975,54.075 54.975,46.325 54.7,46.05 52.95,46.05 52.5,46.5
  pour cut-out: 47.27,57.7 47.737,58.167 47.737,60.112 47.875,60.25 49,60.25 51.025,58.225 52.05,58.225 52.275,58.45 52.275,65.65 52.425,65.8 48.8,65.8 48.1,65.1 44.025,65.1 42.17,63.245 42.17,57.955 42.425,57.7
  pour cut-out: 51.547,35.15 52.075,35.678 52.075,43.15 51.688,43.537 43.587,43.537 42.175,42.125 42.175,35.425 42.45,35.15
  pour cut-out: 50.47,11.47 50.47,14.195 50.8,14.525 51.875,14.525 52.65,13.75 53.65,13.75 53.65,12.25
  pour cut-out: 59.1,13.025 59.1,14.2 61,16.1 62.2,16.1 62.25,16.05 62.25,15.425 62.1,15.275 61.5,15.275 60.675,14.45 60.675,13.525 60.05,12.9 58.975,12.9
  pour cut-out: 55.6,9.75 55.6,8.175 55.675,8.25 57.375,8.25 57.375,7.5 57.475,7.4 61.85,7.4 62.1,7.65 62.1,9 59.85,11.25 59.15,11.25 57.975,10.075 56.15,10.075
  pour cut-out: 49.875,8.275 49.875,6.611 50.375,6.111 50.375,6.075 52.725,8.425 54.575,8.425 55.4,9.25 55.4,10 51.6,10
  pour cut-out: 46.4,6 46.4,5.65 48.75,3.3 49.25,3.3 49.25,3.675 46.925,6
  pour cut-out: 67.225,41.55 67.225,41.625 77.35,41.625 77.85,42.125 96.2,42.125 96.675,41.65 100.05,38.275 100,38.225 100,31.075 96.55,27.625 92.175,27.625 91.025,26.475 90.875,26.475 80.8,26.475 77.125,30.15 67.225,30.125
  text "1" at 123.175,17.55 h1.5 r90
Signal Layer 1:
  pour cut-out: 117,97.4 128.05,97.4 128.05,83 117,83
  text "2" at 123.175,18.8 h1.5 r90
Signal Layer 2:
  pour cut-out: 117,97.4 128.05,97.4 128.05,83 117,83
  pour cut-out: 86.5,20.95 87.55,20.95 87.025,21.475 84.925,21.475 81.7,18.25 68.925,18.25 66.1,15.425 66.1,13.575 66.625,13.05 70.2,16.625 82.175,16.625
  pour cut-out: 73.7,19.725 73.475,19.5 73.475,19.45 72.25,19.45 71.95,19.725 54.425,19.725 53.2,18.5 48.65,18.5 48.463,18.688 48.125,19 35.775,19 35.775,20.375 36.275,20.875 37.7,20.875 37.7,19.725 52.631,19.725 54.255,21.625 73.7,21.625
  pour cut-out: 22.875,58.775 39.175,58.775 39.575,59.175 41.3,59.175 41.7,58.775 41.862,58.937 45.363,58.937 45.625,58.675 45.25,58.3 23.35,58.3
  pour cut-out: 21.675,74 21,73.325 21,72.25 19.75,71 19.75,70.5 21.75,68.5 22.5,68.55 48.925,68.55 49.4,68.075 68.95,68.075 69.475,68.6 68.825,69.25 64.6,69.25 63.575,70.275 58.05,70.275 56.7,71.625 56.7,73.3 56,74
  pour cut-out: 33.975,84.375 55.1,84.375 55.75,83.725 65.65,83.725 66.05,83.325 65.6,82.875 33.75,82.875 33.075,83.55
  pour cut-out: 44.6,78.925 89.355,78.925 89.997,78.283 89.997,78.117 89.792,78.117 89.575,77.9 89.075,78.4 66.655,78.4 65.905,77.65 65.905,77.42 66.275,77.05 66.85,77.05 66.875,77.025 66.875,76.55 66.775,76.45 62.675,76.45 62.1,75.875 62.35,75.625 80.814,75.625 81.148,75.291 80.982,75.125 71.625,75.125 70.15,73.65 70.075,73.725 63.25,73.725 62.8,74.175 50.1,74.175 48.925,75.35 48.925,77 48,77.925 44.625,77.925
  pour cut-out: 47.625,81.3 48.325,82 50.525,82 50.525,81.525 50.525,81.475 50.525,81.1 50.65,80.975 51.755,80.975 51.65,80.87 51.65,80.45 31.65,80.552 31.65,81 31.625,81.025 29.85,81.025 29.175,81.7 29.175,82.225 32.888,82.225 33.844,81.3
  pour cut-out: 48.7,80.15 58,80.15 58.15,80 58.15,79.525 58.125,79.5 48.825,79.5
  text "3" at 123.175,20.05 h1.5 r90
Signal Layer 3:
  pour cut-out: 117,97.4 128.05,97.4 128.05,83 117,83
  text "4" at 123.175,21.3 h1.5 r90
Signal Layer 4:
  pour cut-out: 117,97.4 128.05,97.4 128.05,83 117,83
  text "5" at 123.175,22.55 h1.5 r90
Bottom Layer:
  pour cut-out: 47.125,29.525 47.125,27.7 47.225,27.7 47.225,29.525
  pour cut-out: 93.05,27.15 97.829,31.929 97.829,36.37 94.474,39.725 89.85,39.725 89.579,39.996 89.579,43.7 88.546,44.734 78.959,44.734 78.149,43.924 78.149,42.374 77.324,41.549 77.324,39.325 75.024,37.025 75.024,35.315 75.024,33.95 75.024,33.396 77.575,30.845 77.575,26.625 81.125,23.075 88.975,23.075
  pour cut-out: 77.245,32.061 77.245,26.786 78.02,26.011 78.398,26.011 78.71,26.323 78.71,30.696 77.97,31.436 77.97,32.261 77.345,32.261 77.245,32.361
  pour cut-out: 29.126,79.486 29.95,78.662 29.95,30 29.126,30
  pour cut-out: 28.676,48.277 29.125,47.829 29.125,30.896 28.791,30.563 28.687,30.563 28.35,30.9 28.35,47.951
  pour cut-out: 117,97.4 128.05,97.4 128.05,83 117,83
  pour cut-out: 106.475,73.7 106.475,75.025 107.075,75.625 107.075,85.55 106.475,86.15 104.25,86.15 104.05,86.35 104.05,92.675 103.975,92.75 103.375,92.75 103.375,86 101.625,84.25 101.625,75.225 103.675,73.175 105.975,73.175
  pour cut-out: 54.325,46 54.325,50.45 52.3,52.475 52.3,56.75 51.525,57.525 51.525,74.175 51.95,74.6 51.95,76.35 51.025,77.275 49.25,77.275 48.775,76.8 48.775,66.2 48.325,65.75 48.325,60.175 48.375,60.125 49.075,60.125 50.388,58.812 50.388,55.588 49.6,54.8 49.6,49.55 49.725,49.55 53.275,46
  pour cut-out: 29.775,79.975 30.875,79.975 31.15,80.25 30.95,80.45 30.95,86.95 30.3,87.6 26.95,87.6 26.55,87.2 26.55,82.225 27.125,81.65 27.125,79 27.975,78.15 29.175,78.15 29.95,78.925 29.95,79.3
  pour cut-out: 67.6,43 68.325,43 69.425,41.9 69.425,39.2 69.739,38.886 69.816,38.886 69.816,38.637 69.529,38.35 68.825,38.35 68.575,38.6 68.575,41.425 67.6,42.4
  text "6" at 123.175,23.8 h1.5 r90
Multi-Layer:
  pour cut-out: 121.8,17.425 123.55,17.425 123.55,25.05 121.8,25.05

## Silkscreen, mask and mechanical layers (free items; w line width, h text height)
Top Overlay:
  lines w0.1: 44.05,36.05 50.1,36.05 50.375,36.325 50.375,44.3 ; 28.825,19.85 28.825,28.15 46.725,28.15 46.725,19.85 28.825,19.85 ; 48.85,44.3 55.925,44.3 56.175,44.3 56.175,47.325 48.85,47.325 48.85,44.3
  lines w0.12: 34.4,90.55 34.8,90.55 34.8,90.15
  text "H" at 49.725,83.025 h20
  text "S" at 81.225,81.075 h12
  text "E" at 54.3,73.6 h15
  text "F" at 44.35,73.05 h15
  text "ETH2" at 17.125,70.125 h2
  text "J" at 64.5,60.2 h20
  text "MB2503A" at 64.1,57 h3
  text "I" at 53.95,49.35 h15
  text "G" at 72,48.75 h12
  text "C" at 60.9,48.35 h15
  text "ETH1" at 17.225,47.575 h2
  text "PWR_IN" at 0.65,21.85 h1.5
  text "STPMIC1L : 17.5mm x 8.15mm = 142.5mm²" at 28.95,18.85 h1
Bottom Overlay:
  lines w0.1: 44.75,48.05 55.325,48.05 57.375,50.1 65.3,50.1 65.3,28.225 43.8,28.225 43.8,48.05 44.8,48.05 ; 65.325,36.875 68.725,36.875 ; 68.375,36.525 68.725,36.875 ; 68.375,37.225 68.725,36.875
  lines w0.12: 5.175,30.95 1.995,30.95 1.995,47.05 5.175,47.05 ; 5.175,53.48 1.995,53.48 1.995,69.58 5.175,69.58 ; 9.375,30.95 13.25,30.95 ; 9.375,47.05 13.25,47.05 ; 9.375,69.58 13.35,69.58
  text "USER1" at 0.45,84.3 h1.5 r270
  text "USER2" at 0.45,74.1 h1.5 r270
  text "ETH2" at 11.175,61.25 h3
  text "RESERVED" at 121.15,42.225 h1.5 r270
  text "ETH1" at 10.875,37.95 h3
  text "USB_STLINK" at 120.8,31.75 h1.5 r270
  text "BOOT1" at 37.407,13.825 h1.5 r270
  text "BOOT2" at 34.857,13.8 h1.5 r270
  text "BOOT0" at 39.832,13.725 h1.5 r270
  text "WAKE_UP" at 67.9,2.275 h1.5
  text "TAMPER" at 51.475,2.225 h1.5
  text "RESET" at 59.2,2.225 h1.5
Top Solder:
  region: 114.325,24.8 114.325,23.825 115.3,23.825 115.3,24.8
  region: 115.3,22.975 114.325,22.975 114.325,22 115.3,22
  region: 113.475,22 113.475,22.975 112.5,22.975 112.5,22
  rectangle: 112.5,23.825 113.475,24.8
  region: 56.825,14.75 56.825,13.175 58.4,13.175 58.4,14.75
  region: 58.4,12.325 56.825,12.325 56.825,10.75 58.4,10.75
  region: 55.975,10.75 55.975,12.325 54.4,12.325 54.4,10.75
  rectangle: 54.4,13.175 55.975,14.75
  region: 15.8,25.05 15.275,25.05 15.275,24.075 15.8,24.075
  rectangle: 14.05,22.4 14.575,23.375
  region: 15.8,23.375 15.275,23.375 15.275,22.4 15.8,22.4
  rectangle: 14.05,24.075 14.575,25.05
  region: 47.675,38.6 46.75,38.6 46.75,37.675 47.675,37.675
  region: 45.9,37.675 45.9,38.6 44.975,38.6 44.975,37.675
  rectangle: 44.975,39.45 45.9,40.375
  region: 46.75,40.375 46.75,39.45 47.675,39.45 47.675,40.375
  region: 46.75,62.75 46.75,61.825 47.675,61.825 47.675,62.75
  region: 47.675,60.975 46.75,60.975 46.75,60.05 47.675,60.05
  region: 45.9,60.05 45.9,60.975 44.975,60.975 44.975,60.05
  rectangle: 44.975,61.825 45.9,62.75
  rectangle: 69.05,79.2 70.8,80.95
  rectangle: 66.45,79.2 68.2,80.95
  rectangle: 69.05,81.8 70.8,83.55
  rectangle: 66.45,81.8 68.2,83.55
  rectangle: 106.75,62.325 107.3,65.425
  rectangle: 105.6,62.325 106.15,65.425
  rectangle: 24.586,75.487 26.013,85.013
  rectangle: 18.936,75.487 20.363,85.013
  region: 121.8,17.425 123.55,17.425 123.55,25.05 121.8,25.05
Bottom Solder:
  region: 121.8,17.425 123.55,17.425 123.55,25.05 121.8,25.05
M1-Board Shape:
  the board outline again, w0.1
M7-Top Info:
  text "Raspberry shield standard max width is 65mm" at 53.5,103.038 h1.8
